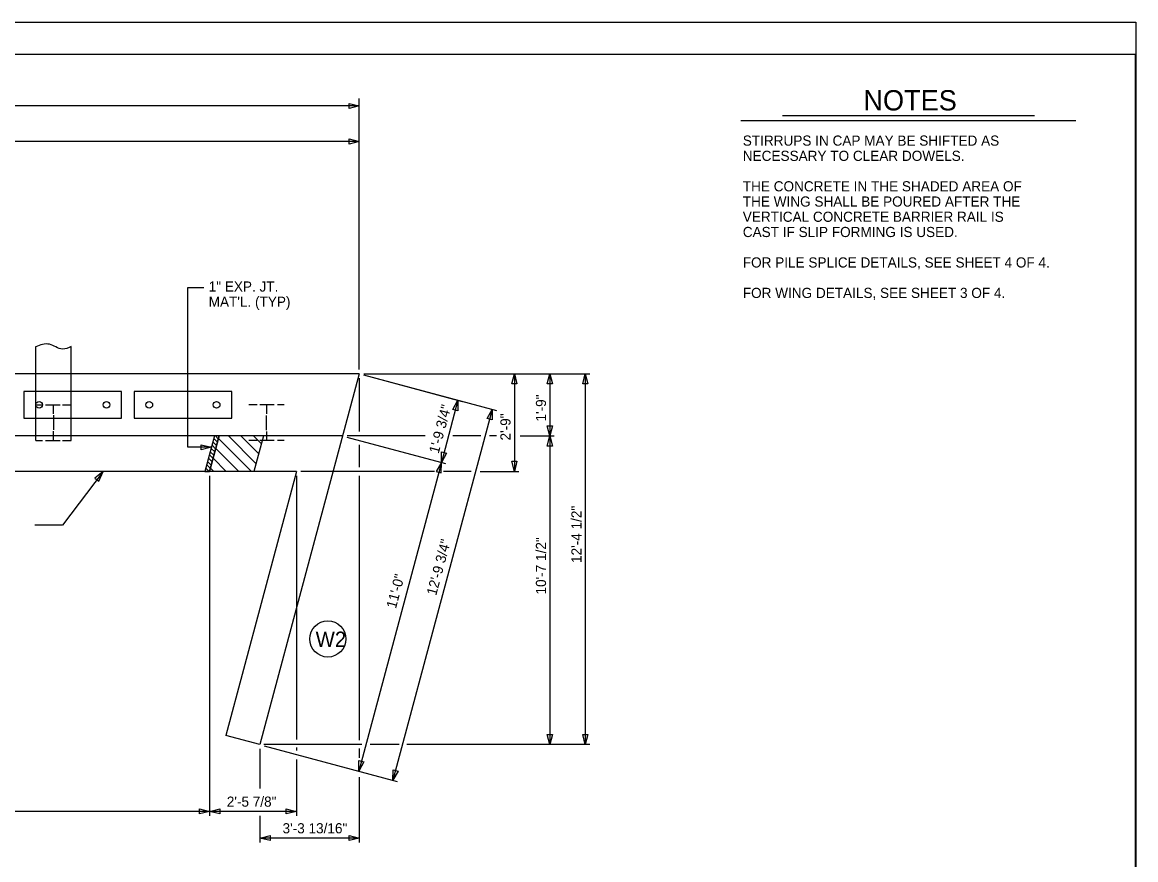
# Model space of a CAD drawing. Extents: x -41 to 191, y -168 to 6.
# Drawn here: x 44.34 to 75.71, y -23.59 to 0 of the extents above; entities that cross this region are included whole.
import ezdxf

# ---------------------------------------------------------------- set-up
doc = ezdxf.new("R2010")
doc.units = 0
for name, color, linetype in [('Arrowhead Terminators CELL', 7, 'Continuous'), ('Dimension Lines', 7, 'Continuous'), ('Mis Object Lines', 7, 'Continuous'), ('Miscellaneous Lines', 7, 'Continuous'), ('Plan Sheet CELL', 7, 'Continuous'), ('Plot Shape CELL', 7, 'Continuous'), ('Rebar Lines', 7, 'Continuous'), ('Structural Steel Lines', 7, 'Continuous'), ('Subtitle Text', 7, 'Continuous'), ('Text', 7, 'Continuous'), ('Title Text', 7, 'Continuous')]:
    doc.layers.add(name, color=color, linetype=linetype)

msp = doc.modelspace()

# ---------------------------------------------------------------- linework, layer by layer
at = {"layer": 'Arrowhead Terminators CELL'}
for points in [[(53.837, -2.358), (53.551, -2.429), (53.551, -2.286)], [(53.837, -3.358), (53.551, -3.429), (53.551, -3.286)], [(58.206, -9.902), (58.277, -10.188), (58.134, -10.188)], [(59.206, -9.902), (59.277, -10.188), (59.134, -10.188)], [(60.206, -9.902), (60.277, -10.188), (60.134, -10.188)], [(56.618, -10.647), (56.613, -10.942), (56.475, -10.905)], [(57.584, -10.906), (57.579, -11.201), (57.441, -11.164)], [(59.206, -11.652), (59.134, -11.365), (59.277, -11.365)], [(49.669, -11.97), (49.383, -12.042), (49.383, -11.899)], [(59.206, -11.652), (59.277, -11.938), (59.134, -11.938)], [(56.149, -12.397), (56.154, -12.102), (56.292, -12.139)], [(56.149, -12.397), (56.006, -12.655), (56.144, -12.692)], [(58.206, -12.652), (58.134, -12.365), (58.277, -12.365)], [(46.617, -12.652), (46.387, -12.837), (46.501, -12.923)], [(59.206, -20.345), (59.134, -20.059), (59.277, -20.059)], [(60.206, -20.345), (60.134, -20.059), (60.277, -20.059)], [(53.82, -21.09), (53.825, -20.795), (53.963, -20.832)], [(54.786, -21.349), (54.791, -21.054), (54.929, -21.091)], [(49.619, -22.23), (49.332, -22.301), (49.332, -22.158)], [(49.619, -22.23), (49.905, -22.158), (49.905, -22.301)], [(52.065, -22.23), (51.779, -22.301), (51.779, -22.158)], [(51.039, -22.98), (51.325, -22.908), (51.325, -23.051)], [(53.837, -22.98), (53.551, -23.051), (53.551, -22.908)]]:
    msp.add_lwpolyline(points, close=True, dxfattribs=at)
at = {"layer": 'Dimension Lines'}
for p, q in [((53.837, -9.777), (53.837, -2.144)), ((53.837, -2.358), (13.337, -2.358)), ((53.837, -3.358), (32.837, -3.358)), ((49.003, -11.97), (49.003, -7.47)), ((49.003, -7.47), (49.453, -7.47)), ((53.837, -10.027), (53.837, -11.527)), ((53.958, -9.934), (57.705, -10.938)), ((53.958, -9.934), (56.739, -10.679)), ((53.962, -9.902), (60.331, -9.902)), ((58.206, -9.902), (58.206, -12.652)), ((59.206, -9.902), (59.206, -11.652)), ((60.206, -9.902), (60.206, -20.345)), ((56.618, -10.647), (56.149, -12.397)), ((57.584, -10.906), (54.786, -21.349)), ((49.688, -11.909), (49.79, -12.011)), ((49.713, -11.816), (49.815, -11.918)), ((49.738, -11.723), (49.84, -11.825)), ((49.784, -11.652), (49.865, -11.732)), ((50.796, -12.652), (49.868, -11.723)), ((50.925, -12.426), (50.15, -11.652)), ((50.194, -11.648), (50.197, -11.652)), ((50.999, -12.147), (50.504, -11.652)), ((51.074, -11.869), (50.857, -11.652)), ((53.489, -11.684), (56.27, -12.429)), ((55.697, -11.652), (53.493, -11.652)), ((53.837, -11.902), (53.837, -12.527)), ((57.259, -11.652), (56.474, -11.652)), ((57.703, -11.652), (57.509, -11.652)), ((58.371, -11.652), (59.331, -11.652)), ((59.206, -11.652), (59.206, -20.345)), ((49.669, -11.97), (49.003, -11.97)), ((49.614, -12.188), (49.716, -12.29)), ((49.638, -12.095), (49.74, -12.197)), ((49.663, -12.002), (49.765, -12.104)), ((50.443, -12.652), (49.793, -12.002)), ((49.539, -12.467), (49.641, -12.569)), ((49.564, -12.374), (49.666, -12.476)), ((49.589, -12.281), (49.691, -12.383)), ((50.089, -12.652), (49.718, -12.28)), ((56.149, -12.397), (53.82, -21.09)), ((49.514, -12.56), (49.606, -12.652)), ((49.619, -12.777), (49.619, -22.355)), ((49.736, -12.652), (49.643, -12.559)), ((52.065, -12.777), (52.065, -20.206)), ((55.956, -12.652), (52.19, -12.652)), ((53.837, -12.777), (53.837, -20.224)), ((56.991, -12.652), (56.206, -12.652)), ((57.241, -12.652), (58.331, -12.652)), ((53.909, -20.345), (51.147, -20.345)), ((51.16, -20.377), (54.906, -21.381)), ((54.962, -20.345), (54.145, -20.345)), ((60.331, -20.345), (55.175, -20.345)), ((51.039, -20.47), (51.039, -21.587)), ((52.065, -20.424), (52.065, -20.515)), ((53.837, -20.46), (53.837, -20.715)), ((52.065, -20.769), (52.065, -22.355)), ((53.837, -21.26), (53.837, -23.105)), ((49.619, -22.23), (32.837, -22.23)), ((52.065, -22.23), (49.619, -22.23)), ((51.039, -22.355), (51.039, -23.105)), ((53.837, -22.98), (51.039, -22.98))]:
    msp.add_line(p, q, dxfattribs=at)
msp.add_lwpolyline([(49.887, -11.652), (49.757, -11.652), (49.489, -12.652), (49.619, -12.652)], close=True, dxfattribs=at)
msp.add_lwpolyline([(46.617, -12.652), (45.473, -14.161), (44.696, -14.161)], dxfattribs=at)
msp.add_circle((52.952, -17.371), 0.509, dxfattribs=at)
at = {"layer": 'Mis Object Lines'}
for p, q in [((53.837, -9.902), (35.756, -9.902)), ((53.837, -9.902), (51.039, -20.345)), ((49.887, -11.652), (16.325, -11.652)), ((49.887, -11.652), (49.619, -12.652)), ((53.368, -11.652), (49.887, -11.652)), ((51.138, -11.652), (50.87, -12.652)), ((52.065, -12.652), (13.636, -12.652)), ((52.065, -12.652), (50.073, -20.086)), ((51.039, -20.345), (50.073, -20.086))]:
    msp.add_line(p, q, dxfattribs=at)
at = {"layer": 'Miscellaneous Lines'}
for points in [[(44.388, -11.152), (47.138, -11.152), (47.138, -10.402), (44.388, -10.402)], [(47.494, -11.152), (50.244, -11.152), (50.244, -10.402), (47.494, -10.402)]]:
    msp.add_lwpolyline(points, close=True, dxfattribs=at)
at = {"layer": 'Plan Sheet CELL'}
for p, q in [((75.715, 0), (75.715, 0)), ((2.414, -0.902), (75.694, -0.902)), ((75.694, -0.902), (75.694, -48.992))]:
    msp.add_line(p, q, dxfattribs=at)
at = {"layer": 'Plot Shape CELL'}
msp.add_lwpolyline([(0, 0), (75.715, 0), (75.715, -50.38), (0, -50.38)], close=True, dxfattribs=at)
at = {"layer": 'Rebar Lines'}
for points in [[(50.964, -10.776), (50.721, -10.776)], [(51.443, -10.776), (51.035, -10.776)], [(51.219, -10.776), (51.219, -11.033)], [(51.721, -10.776), (51.53, -10.776)], [(51.219, -11.276), (51.219, -11.077)], [(51.219, -11.489), (51.219, -11.277)], [(51.219, -11.528), (51.219, -11.776)], [(50.964, -11.776), (50.721, -11.776)], [(51.443, -11.776), (51.035, -11.776)], [(51.721, -11.776), (51.53, -11.776)]]:
    msp.add_lwpolyline(points, dxfattribs=at)
for centre in [(44.814, -10.777), (46.712, -10.777), (47.92, -10.777), (49.818, -10.777)]:
    msp.add_circle(centre, 0.0938, dxfattribs=at)
at = {"layer": 'Structural Steel Lines'}
for p, q in [((44.721, -11.777), (44.721, -9.136)), ((45.721, -11.777), (45.721, -9.136))]:
    msp.add_line(p, q, dxfattribs=at)
for points in [[(44.721, -10.777), (44.912, -10.777)], [(44.999, -10.777), (45.407, -10.777)], [(45.223, -11.025), (45.223, -10.777)], [(45.478, -10.777), (45.721, -10.777)], [(45.223, -11.063), (45.223, -11.276)], [(45.223, -11.277), (45.223, -11.476)], [(45.223, -11.777), (45.223, -11.52)], [(44.721, -11.777), (44.912, -11.777)], [(44.999, -11.777), (45.407, -11.777)], [(45.478, -11.777), (45.721, -11.777)]]:
    msp.add_lwpolyline(points, dxfattribs=at)
msp.add_spline([(45.721, -9.136), (45.477, -9.206), (45.104, -9.069), (44.721, -9.14)], degree=3, dxfattribs=at)
at = {"layer": 'Title Text'}
for p, q in [((64.592, -2.768), (74.027, -2.768)), ((65.76, -2.626), (72.859, -2.626))]:
    msp.add_line(p, q, dxfattribs=at)

# ---------------------------------------------------------------- texts
at = {"layer": 'Subtitle Text'}
for s, height, p in [('STIRRUPS IN CAP MAY BE SHIFTED AS', 0.286, (64.643, -3.476)), ('NECESSARY TO CLEAR DOWELS.', 0.286, (64.643, -3.905)), ('THE CONCRETE IN THE SHADED AREA OF', 0.286, (64.643, -4.763)), ('THE WING SHALL BE POURED AFTER THE', 0.286, (64.643, -5.192)), ('VERTICAL CONCRETE BARRIER RAIL IS', 0.286, (64.643, -5.621)), ('CAST IF SLIP FORMING IS USED.', 0.286, (64.643, -6.05)), ('FOR PILE SPLICE DETAILS, SEE SHEET 4 OF 4.', 0.286, (64.643, -6.908)), ('FOR WING DETAILS, SEE SHEET 3 OF 4.', 0.286, (64.643, -7.766)), ('W2', 0.429, (52.607, -17.593))]:
    msp.add_text(s, height=height, dxfattribs=at).set_placement(p)
at = {"layer": 'Text'}
for s, p in [('1" EXP. JT.', (49.594, -7.586)), ("MAT'L. (TYP)", (49.594, -8.015)), ('3\'-3 13/16"', (51.675, -22.846))]:
    msp.add_text(s, height=0.286, dxfattribs=at).set_placement(p)
for s, rotation, p in [('1\'-9"', 90, (59.099, -11.246)), ('1\'-9 3/4"', 75, (56.072, -12.168)), ('2\'-9"', 90, (58.099, -11.78)), ('12\'-4 1/2"', 90, (60.099, -15.231)), ('12\'-9 3/4"', 75, (56.003, -16.165)), ('10\'-7 1/2"', 90, (59.099, -16.118)), ('11\'-0"', 75, (54.869, -16.532)), ('2\'-5 7/8"', 0, (50.104, -22.096))]:
    msp.add_text(s, height=0.286, rotation=rotation, dxfattribs=at).set_placement(p)
at = {"layer": 'Title Text'}
msp.add_text('NOTES', height=0.5714, dxfattribs=at).set_placement((68.041, -2.483))

doc.saveas('drawing.dxf')
